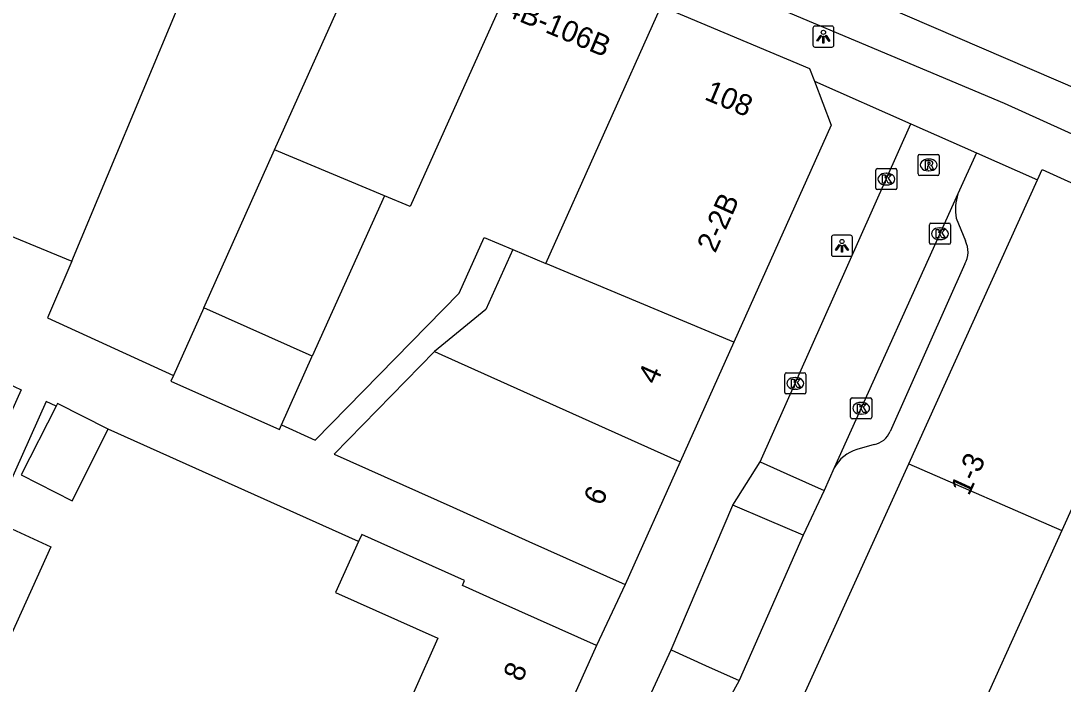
# Model space of a CAD drawing. Extents: x 161845 to 162341, y 381620 to 382158.
# Drawn here: x 162150.69 to 162200.09, y 381787.37 to 381818.81 of the extents above; entities that cross this region are included whole.
import ezdxf

# ---------------------------------------------------------------- set-up
doc = ezdxf.new("R2010")
doc.units = 0
for name, color, linetype in [('IMGEO_Kolk', 7, 'Continuous'), ('IMGEO_Lichtpunt', 7, 'Continuous'), ('IMGEO_Pand', 7, 'Continuous'), ('IMGEO_Pand_nummerreeks', 7, 'Continuous'), ('IMGEO_Rijbaan_lokaal_open', 7, 'Continuous'), ('IMGEO_Rioolput', 7, 'Continuous'), ('IMGEO_Voetpad_gesloten', 7, 'Continuous'), ('IMGEO_Voetpad_open', 7, 'Continuous')]:
    doc.layers.add(name, color=color, linetype=linetype)

msp = doc.modelspace()

# ---------------------------------------------------------------- linework, layer by layer
at = {"layer": 'IMGEO_Kolk'}
for p, q in [((162191.211, 381810.882), (162191.211, 381811.734)), ((162191.286, 381811.808), (162192.138, 381811.808)), ((162192.212, 381811.734), (162192.212, 381810.882)), ((162191.699, 381811.588), (162191.724, 381811.588)), ((162192.138, 381810.808), (162191.286, 381810.808)), ((162191.722, 381811.028), (162191.697, 381811.028)), ((162193.824, 381809.219), (162194.676, 381809.219)), ((162193.749, 381808.293), (162193.749, 381809.145)), ((162194.237, 381808.999), (162194.262, 381808.999)), ((162194.75, 381809.145), (162194.75, 381808.293)), ((162194.676, 381808.219), (162193.824, 381808.219)), ((162194.26, 381808.439), (162194.235, 381808.439)), ((162186.893, 381801.2), (162186.893, 381802.052)), ((162186.968, 381802.126), (162187.82, 381802.126)), ((162187.381, 381801.906), (162187.406, 381801.906)), ((162187.894, 381802.052), (162187.894, 381801.2)), ((162187.404, 381801.346), (162187.379, 381801.346)), ((162187.82, 381801.126), (162186.968, 381801.126)), ((162190.017, 381800.022), (162190.017, 381800.874)), ((162190.092, 381800.948), (162190.944, 381800.948)), ((162191.018, 381800.874), (162191.018, 381800.022)), ((162190.505, 381800.728), (162190.53, 381800.728)), ((162190.944, 381799.948), (162190.092, 381799.948)), ((162190.528, 381800.168), (162190.503, 381800.168))]:
    msp.add_line(p, q, dxfattribs=at)
for points in [[(162191.211, 381810.882), (162191.211, 381811.734)], [(162191.286, 381811.808), (162192.138, 381811.808)], [(162192.212, 381811.734), (162192.212, 381810.882)], [(162191.532, 381811.508), (162191.655, 381811.508), (162191.655, 381811.357), (162191.785, 381811.508), (162191.949, 381811.508), (162191.803, 381811.357), (162191.956, 381811.108), (162191.804, 381811.108), (162191.719, 381811.272), (162191.655, 381811.205), (162191.655, 381811.108), (162191.532, 381811.108), (162191.532, 381811.508)], [(162192.138, 381810.808), (162191.286, 381810.808)], [(162193.824, 381809.219), (162194.676, 381809.219)], [(162193.749, 381808.293), (162193.749, 381809.145)], [(162194.07, 381808.919), (162194.193, 381808.919), (162194.193, 381808.768), (162194.323, 381808.919), (162194.487, 381808.919), (162194.341, 381808.768), (162194.494, 381808.519), (162194.342, 381808.519), (162194.257, 381808.683), (162194.193, 381808.616), (162194.193, 381808.519), (162194.07, 381808.519), (162194.07, 381808.919)], [(162194.75, 381809.145), (162194.75, 381808.293)], [(162194.676, 381808.219), (162193.824, 381808.219)], [(162186.893, 381801.2), (162186.893, 381802.052)], [(162186.968, 381802.126), (162187.82, 381802.126)], [(162187.214, 381801.826), (162187.337, 381801.826), (162187.337, 381801.675), (162187.467, 381801.826), (162187.631, 381801.826), (162187.485, 381801.675), (162187.638, 381801.426), (162187.486, 381801.426), (162187.401, 381801.59), (162187.337, 381801.523), (162187.337, 381801.426), (162187.214, 381801.426), (162187.214, 381801.826)], [(162187.894, 381802.052), (162187.894, 381801.2)], [(162187.82, 381801.126), (162186.968, 381801.126)], [(162190.017, 381800.022), (162190.017, 381800.874)], [(162190.092, 381800.948), (162190.944, 381800.948)], [(162191.018, 381800.874), (162191.018, 381800.022)], [(162190.338, 381800.648), (162190.461, 381800.648), (162190.461, 381800.497), (162190.591, 381800.648), (162190.755, 381800.648), (162190.609, 381800.497), (162190.762, 381800.248), (162190.61, 381800.248), (162190.525, 381800.412), (162190.461, 381800.345), (162190.461, 381800.248), (162190.338, 381800.248), (162190.338, 381800.648)], [(162190.944, 381799.948), (162190.092, 381799.948)]]:
    msp.add_lwpolyline(points, dxfattribs=at)
for centre, start, end in [((162191.288, 381811.732), 91.552, 178.448), ((162191.288, 381811.732), 91.552, 178.448), ((162192.136, 381811.732), 1.552, 88.448), ((162192.136, 381811.732), 1.552, 88.448), ((162191.288, 381810.884), 181.552, 268.448), ((162191.288, 381810.884), 181.552, 268.448), ((162192.136, 381810.884), 271.552, 358.448), ((162192.136, 381810.884), 271.552, 358.448), ((162193.826, 381809.143), 91.552, 178.448), ((162193.826, 381809.143), 91.552, 178.448), ((162194.674, 381809.143), 1.552, 88.448), ((162194.674, 381809.143), 1.552, 88.448), ((162193.826, 381808.295), 181.552, 268.448), ((162193.826, 381808.295), 181.552, 268.448), ((162194.674, 381808.295), 271.552, 358.448), ((162194.674, 381808.295), 271.552, 358.448), ((162186.97, 381802.05), 91.552, 178.448), ((162186.97, 381802.05), 91.552, 178.448), ((162187.818, 381802.05), 1.552, 88.448), ((162187.818, 381802.05), 1.552, 88.448), ((162186.97, 381801.202), 181.552, 268.448), ((162186.97, 381801.202), 181.552, 268.448), ((162187.818, 381801.202), 271.552, 358.448), ((162187.818, 381801.202), 271.552, 358.448), ((162190.094, 381800.872), 91.552, 178.448), ((162190.094, 381800.872), 91.552, 178.448), ((162190.942, 381800.872), 1.552, 88.448), ((162190.942, 381800.872), 1.552, 88.448), ((162190.094, 381800.024), 181.552, 268.448), ((162190.094, 381800.024), 181.552, 268.448), ((162190.942, 381800.024), 271.552, 358.448), ((162190.942, 381800.024), 271.552, 358.448)]:
    msp.add_arc(centre, 0.0765, start, end, dxfattribs=at)
for centre, major_axis, ratio, start_param, end_param in [((162191.698, 381811.308), (-0.387, 0.002), 0.722429, 4.712389, 7.853982), ((162191.723, 381811.308), (-0.39, 0.002), 0.717154, 1.570796, 4.712389), ((162194.236, 381808.719), (-0.387, 0.002), 0.722429, 4.712389, 7.853982), ((162194.261, 381808.719), (-0.39, 0.002), 0.717154, 1.570796, 4.712389), ((162187.38, 381801.626), (-0.387, 0.002), 0.722429, 4.712389, 7.853982), ((162187.405, 381801.626), (-0.39, 0.002), 0.717154, 1.570796, 4.712389), ((162190.504, 381800.448), (-0.387, 0.002), 0.722429, 4.712389, 7.853982), ((162190.529, 381800.448), (-0.39, 0.002), 0.717154, 1.570796, 4.712389)]:
    msp.add_ellipse(centre, major_axis=major_axis, ratio=ratio, start_param=start_param, end_param=end_param, dxfattribs=at)
at = {"layer": 'IMGEO_Lichtpunt'}
for p, q in [((162189.13, 381818.558), (162188.322, 381818.558)), ((162189.13, 381818.558), (162188.322, 381818.558)), ((162188.228, 381818.463), (162188.228, 381817.656)), ((162188.228, 381818.463), (162188.228, 381817.656)), ((162189.224, 381817.656), (162189.224, 381818.463)), ((162189.224, 381817.656), (162189.224, 381818.463)), ((162188.322, 381817.562), (162189.13, 381817.562)), ((162188.322, 381817.562), (162189.13, 381817.562)), ((162189.107, 381808.552), (162189.107, 381807.745)), ((162189.107, 381808.552), (162189.107, 381807.745)), ((162190.009, 381808.647), (162189.201, 381808.647)), ((162190.009, 381808.647), (162189.201, 381808.647)), ((162190.103, 381807.745), (162190.103, 381808.552)), ((162190.103, 381807.745), (162190.103, 381808.552)), ((162189.201, 381807.651), (162190.009, 381807.651)), ((162189.201, 381807.651), (162190.009, 381807.651))]:
    msp.add_line(p, q, dxfattribs=at)
for points in [[(162188.602, 381818.127), (162188.641, 381818.099), (162188.453, 381817.837), (162188.415, 381817.864), (162188.602, 381818.127)], [(162188.704, 381818.079), (162188.751, 381818.079), (162188.751, 381817.757), (162188.704, 381817.757), (162188.704, 381818.079)], [(162188.814, 381818.099), (162188.852, 381818.126), (162189.039, 381817.864), (162189, 381817.836), (162188.814, 381818.099)], [(162189.481, 381808.216), (162189.52, 381808.188), (162189.332, 381807.926), (162189.294, 381807.953), (162189.481, 381808.216)], [(162189.583, 381808.168), (162189.63, 381808.168), (162189.63, 381807.846), (162189.583, 381807.846), (162189.583, 381808.168)], [(162189.693, 381808.188), (162189.731, 381808.215), (162189.918, 381807.953), (162189.879, 381807.925), (162189.693, 381808.188)]]:
    msp.add_lwpolyline(points, dxfattribs=at)
for centre in [(162188.727, 381818.261), (162189.606, 381808.35)]:
    msp.add_circle(centre, 0.0994, dxfattribs=at)
for centre, start, end in [((162188.322, 381818.463), 90, 180), ((162188.322, 381818.463), 90, 180), ((162189.13, 381818.463), 0, 90), ((162189.13, 381818.463), 0, 90), ((162188.322, 381817.656), 180, 270), ((162188.322, 381817.656), 180, 270), ((162189.13, 381817.656), 270, 0), ((162189.13, 381817.656), 270, 360), ((162189.201, 381808.552), 90, 180), ((162189.201, 381808.552), 90, 180), ((162190.009, 381808.552), 0, 90), ((162190.009, 381808.552), 0, 90), ((162189.201, 381807.745), 180, 270), ((162189.201, 381807.745), 180, 270), ((162190.009, 381807.745), 270, 0), ((162190.009, 381807.745), 270, 360)]:
    msp.add_arc(centre, 0.0946, start, end, dxfattribs=at)
at = {"layer": 'IMGEO_Pand'}
for points in [[(162153.095, 381807.419), (162161.549, 381827.655)], [(162162.716, 381812.696), (162168.182, 381824.878)], [(162174.599, 381822.191), (162169.133, 381810.009), (162167.915, 381810.519)], [(162175.567, 381807.313), (162181.034, 381819.497)], [(162181.034, 381819.497), (162188.075, 381816.549), (162188.305, 381815.945)], [(162188.305, 381815.945), (162189.098, 381813.863), (162184.484, 381803.578)], [(162159.36, 381805.214), (162162.716, 381812.696)], [(162167.915, 381810.519), (162162.716, 381812.696)], [(162142.94, 381812.435), (162145.297, 381811.453), (162145.01, 381810.757), (162153.095, 381807.419)], [(162198.869, 381811.272), (162199.091, 381811.761), (162206.304, 381808.493)], [(162192.769, 381797.807), (162198.869, 381811.272)], [(162167.915, 381810.519), (162164.502, 381802.912)], [(162163.045, 381799.664), (162164.629, 381798.94), (162171.459, 381805.906), (162172.641, 381808.539), (162174.005, 381807.968)], [(162206.304, 381808.493), (162200.035, 381794.656)], [(162174.005, 381807.968), (162172.729, 381805.127), (162170.3, 381803.138)], [(162174.005, 381807.968), (162175.567, 381807.313)], [(162153.095, 381807.419), (162151.95, 381804.733), (162157.92, 381802.005)], [(162184.484, 381803.578), (162175.567, 381807.313)], [(162159.36, 381805.214), (162157.92, 381802.005)], [(162164.502, 381802.912), (162159.36, 381805.214)], [(162184.484, 381803.578), (162181.945, 381797.916)], [(162163.045, 381799.664), (162164.502, 381802.912)], [(162170.3, 381803.138), (162165.533, 381798.275), (162171.156, 381795.757), (162174.77, 381794.136), (162179.331, 381792.089)], [(162170.3, 381803.138), (162170.646, 381802.983), (162181.945, 381797.916)], [(162157.92, 381802.005), (162157.8, 381801.738), (162162.942, 381799.435), (162163.045, 381799.664)], [(162152.366, 381800.551), (162150.708, 381797.287), (162153.111, 381796.066), (162154.831, 381799.45)], [(162154.831, 381799.45), (162152.427, 381800.671), (162152.366, 381800.551)], [(162181.945, 381797.916), (162179.331, 381792.089)], [(162192.769, 381797.807), (162200.035, 381794.656)], [(162147.772, 381790.915), (162149.622, 381795.011), (162152.11, 381793.887), (162150.263, 381789.796)], [(162177.973, 381789.202), (162173.411, 381791.248), (162171.618, 381792.054), (162171.716, 381792.285), (162166.842, 381794.472), (162166.688, 381794.129)], [(162200.035, 381794.656), (162194.479, 381782.392)], [(162166.688, 381794.129), (162165.607, 381791.72), (162170.45, 381789.548), (162169.293, 381786.97)], [(162177.973, 381789.202), (162175.685, 381784.102), (162175.462, 381784.202)]]:
    msp.add_lwpolyline(points, dxfattribs=at)
at = {"layer": 'IMGEO_Rijbaan_lokaal_open'}
for points in [[(162191.564, 381819.539), (162200.882, 381815.518)], [(162185.736, 381797.906), (162192.878, 381813.922)], [(162192.878, 381813.922), (162195.978, 381812.551)], [(162195.978, 381812.551), (162195.103, 381810.611)], [(162195.103, 381810.611), (162189.241, 381797.618)], [(162184.432, 381795.859), (162185.736, 381797.906)], [(162185.736, 381797.906), (162186.991, 381797.344), (162188.76, 381796.552)], [(162189.241, 381797.618), (162188.76, 381796.552)], [(162188.76, 381796.552), (162187.772, 381794.43)], [(162181.509, 381788.998), (162184.432, 381795.859)], [(162187.772, 381794.43), (162186.057, 381795.164), (162184.432, 381795.859)], [(162187.772, 381794.43), (162184.735, 381787.543)], [(162180.483, 381786.774), (162181.509, 381788.998)], [(162181.509, 381788.998), (162183.143, 381788.261), (162184.735, 381787.543)], [(162184.735, 381787.543), (162183.583, 381785.445)]]:
    msp.add_lwpolyline(points, dxfattribs=at)
at = {"layer": 'IMGEO_Rioolput'}
for p, q in [((162193.218, 381811.553), (162193.218, 381812.405)), ((162193.293, 381812.479), (162194.145, 381812.479)), ((162193.706, 381812.259), (162193.731, 381812.259)), ((162194.219, 381812.405), (162194.219, 381811.553)), ((162193.729, 381811.699), (162193.704, 381811.699)), ((162194.145, 381811.479), (162193.293, 381811.479))]:
    msp.add_line(p, q, dxfattribs=at)
for points in [[(162193.218, 381811.553), (162193.218, 381812.405)], [(162193.293, 381812.479), (162194.145, 381812.479)], [(162193.807, 381812.177), (162193.555, 381812.179), (162193.555, 381811.779)], [(162194.219, 381812.405), (162194.219, 381811.553)], [(162193.555, 381811.779), (162193.679, 381811.779), (162193.679, 381811.941), (162193.69, 381811.941)], [(162193.733, 381812.098), (162193.679, 381812.098), (162193.679, 381812.017)], [(162193.679, 381812.017), (162193.731, 381812.017)], [(162193.737, 381811.912), (162193.808, 381811.779), (162193.948, 381811.779), (162193.883, 381811.905)], [(162194.145, 381811.479), (162193.293, 381811.479)]]:
    msp.add_lwpolyline(points, dxfattribs=at)
for centre, radius, start, end in [((162193.295, 381812.403), 0.0765, 91.552, 178.448), ((162193.295, 381812.403), 0.0765, 91.552, 178.448), ((162193.806, 381812.067), 0.109, 350.3612, 89.416), ((162194.143, 381812.403), 0.0765, 1.552, 88.448), ((162194.143, 381812.403), 0.0765, 1.552, 88.448), ((162193.689, 381811.888), 0.0533, 26.0293, 88.6989), ((162193.715, 381812.206), 0.19, 274.7715, 282.9687), ((162193.739, 381812.002), 0.0964, 77.0061, 93.1865), ((162193.753, 381812.059), 0.0378, 276.6634, 79.6772), ((162193.804, 381812.067), 0.112, 277.5842, 350.9817), ((162193.788, 381811.852), 0.108, 29.5134, 73.7905), ((162193.295, 381811.555), 0.0765, 181.552, 268.448), ((162193.295, 381811.555), 0.0765, 181.552, 268.448), ((162194.143, 381811.555), 0.0765, 271.552, 358.448), ((162194.143, 381811.555), 0.0765, 271.552, 358.448)]:
    msp.add_arc(centre, radius, start, end, dxfattribs=at)
for centre, major_axis, ratio, start_param, end_param in [((162193.705, 381811.979), (-0.387, 0.002), 0.722429, 4.712389, 7.853982), ((162193.73, 381811.979), (-0.39, 0.002), 0.717154, 1.570796, 4.712389)]:
    msp.add_ellipse(centre, major_axis=major_axis, ratio=ratio, start_param=start_param, end_param=end_param, dxfattribs=at)
at = {"layer": 'IMGEO_Voetpad_gesloten'}
msp.add_lwpolyline([(162289.497, 381752.523), (162284.268, 381764.473), (162282.076, 381768.974), (162280.091, 381772.447), (162277.759, 381775.733), (162275.072, 381778.709), (162271.828, 381781.089), (162266.754, 381783.434), (162197.313, 381814.891), (162168.761, 381826.912), (162165.238, 381828.801), (162160.086, 381831.935), (162154.18, 381835.7), (162147.552, 381840.181), (162140.263, 381845.513), (162134.882, 381849.978)], dxfattribs=at)
at = {"layer": 'IMGEO_Voetpad_open'}
for points in [[(162188.305, 381815.945), (162192.878, 381813.922)], [(162195.978, 381812.551), (162198.869, 381811.272)], [(162195.024, 381809.455), (162195.46, 381808.377)], [(162195.426, 381807.286), (162191.893, 381799.349)], [(162149.358, 381801.946), (162150.709, 381801.321), (162142.742, 381783.559)], [(162152.366, 381800.551), (162151.891, 381800.771), (162148.117, 381792.355), (162144.98, 381785.36)], [(162166.688, 381794.129), (162154.831, 381799.45)], [(162191.134, 381798.724), (162190.31, 381798.492)], [(162187.266, 381785.66), (162192.769, 381797.807)], [(162179.331, 381792.089), (162177.973, 381789.202)]]:
    msp.add_lwpolyline(points, dxfattribs=at)
for centre, radius, start, end in [((162197.269, 381809.882), 2.285, 161.4027, 190.7784), ((162194.434, 381807.863), 1.148, 329.8202, 26.6098), ((162190.916, 381799.762), 1.061, 281.8573, 337.0824), ((162190.823, 381796.774), 1.793, 106.6266, 151.9113)]:
    msp.add_arc(centre, radius, start, end, dxfattribs=at)

# ---------------------------------------------------------------- texts
at = {"layer": 'IMGEO_Pand_nummerreeks'}
for s, rotation, p in [('104B-106B', 337.2135, (162172.205, 381819.663)), ('108', 337.2814, (162183.041, 381815.1)), ('2-2B', 65.8383, (162183.601, 381807.767)), ('4', 65.85, (162180.803, 381801.527)), ('1-3', 65.4261, (162195.624, 381796.264)), ('6', 65.8386, (162178.226, 381795.782)), ('8', 65.8386, (162174.419, 381787.436))]:
    msp.add_text(s, height=1, rotation=rotation, dxfattribs=at).set_placement(p)

doc.saveas('drawing.dxf')
